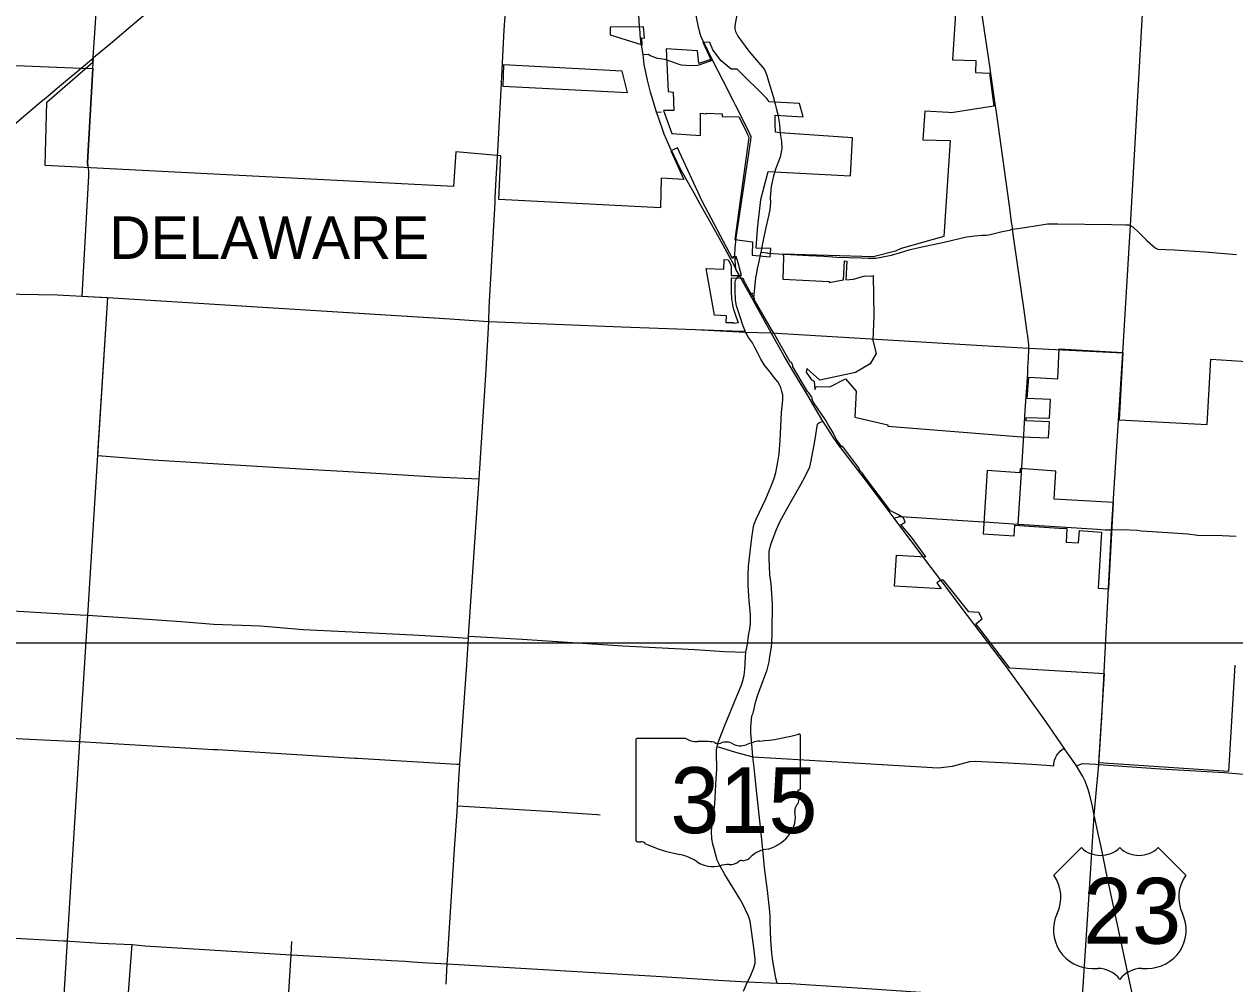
# Model space of a CAD drawing. Extents: x 1729596 to 1925846, y 659247 to 911751.
# Drawn here: x 1796200 to 1821771, y 807237 to 827504 of the extents above; entities that cross this region are included whole.
import ezdxf

# ---------------------------------------------------------------- set-up
doc = ezdxf.new("R2010")
doc.units = 0
for name, color, linetype in [('GM_X_City_Street', 7, 'Continuous'), ('GM_X_Corporation', 7, 'Continuous'), ('GM_X_County_Road', 7, 'Continuous'), ('GM_X_State_Route', 7, 'Continuous'), ('GM_X_State_Shield', 7, 'Continuous'), ('GM_X_Township', 7, 'Continuous'), ('GM_X_Township_Road', 7, 'Continuous'), ('GM_X_Township_Text', 7, 'Continuous'), ('GM_X_US_Route', 7, 'Continuous'), ('GM_X_US_Shield', 7, 'Continuous'), ('SH_Data', 7, 'Continuous')]:
    doc.layers.add(name, color=color, linetype=linetype)

msp = doc.modelspace()

# ---------------------------------------------------------------- linework, layer by layer
at = {"layer": 'GM_X_City_Street'}
for points in [[(1810506, 827220), (1810502, 827229), (1810482, 827281), (1810461, 827356), (1810438, 827474), (1810238, 828490), (1810225, 828549), (1810117, 829066), (1810105, 829126), (1810080, 829357), (1810068, 829471), (1810135, 830154), (1810144, 830257), (1810215, 830861), (1810235, 831013), (1810251, 831109), (1810267, 831292), (1810283, 831379)], [(1806208, 824940), (1806284, 826252), (1806292, 826406), (1806341, 827386), (1806384, 828059), (1806393, 828209), (1806439, 829079), (1806485, 829730)], [(1811339, 828131), (1811336, 828114), (1811291, 827864), (1811232, 827586), (1811211, 827467), (1811213, 827409), (1811226, 827353), (1811276, 827254), (1811353, 827144), (1811508, 826935), (1811666, 826747), (1811796, 826596), (1811839, 826549), (1811877, 826439), (1812017, 825974), (1812059, 825816)], [(1797542, 824510), (1797538, 824584), (1797648, 826566), (1797666, 826798)], [(1809272, 826861), (1809388, 826870), (1809425, 826840), (1809572, 826785), (1809634, 826782), (1809723, 826766), (1809774, 826750)], [(1809554, 825645), (1809661, 825653)], [(1812124, 825562), (1812156, 825394), (1812169, 825198)], [(1812067, 824435), (1812027, 824300), (1811979, 824075), (1811956, 823838), (1811961, 823737), (1811950, 823584), (1811912, 823418), (1811863, 823209), (1811821, 823014), (1811788, 822838)], [(1811218, 822539), (1811212, 822624), (1811214, 822783), (1811229, 822907)], [(1812232, 822643), (1812134, 822648), (1811916, 822664)], [(1811748, 822631), (1811720, 822495), (1811680, 822334), (1811660, 822220), (1811644, 822150), (1811628, 821928), (1811606, 821726)], [(1817270, 818144), (1817313, 818821)], [(1814830, 817099), (1816459, 816996)], [(1818869, 816837), (1819032, 816826), (1819169, 816826), (1819183, 816827)], [(1819183, 816827), (1819368, 816835), (1819716, 816815), (1819794, 816805), (1820031, 816793), (1820776, 816743), (1820982, 816713), (1821507, 816705), (1821800, 816689)]]:
    msp.add_lwpolyline(points, dxfattribs=at)
at = {"layer": 'GM_X_Corporation'}
for points in [[(1821774, 813966), (1821636, 811724), (1818900, 811901), (1819016, 813785), (1817020, 813906), (1816383, 814734), (1816301, 814842), (1816435, 814943), (1816366, 815082), (1816155, 815095), (1815617, 815760), (1815561, 815764), (1815479, 815702), (1815572, 815578), (1814586, 815636), (1814625, 816291), (1815246, 816252), (1814939, 816670), (1814720, 816934), (1814753, 816955), (1814811, 816988), (1814776, 817076), (1814667, 817139), (1814496, 817226), (1813955, 817945), (1813903, 818031), (1813839, 818093), (1813831, 818102), (1813843, 818112), (1813482, 818591), (1813470, 818581), (1813351, 818740), (1813288, 818875), (1813189, 819034), (1813124, 819146), (1812881, 819505), (1812836, 819583), (1812849, 819591), (1812841, 819604), (1812840, 819626), (1812822, 819647), (1812774, 819718), (1812742, 819743), (1812429, 820284), (1812442, 820292), (1812415, 820338), (1812417, 820354), (1812400, 820364), (1812387, 820356), (1812151, 820764), (1812047, 820960), (1811983, 821059), (1811619, 821689), (1811632, 821697), (1811579, 821781), (1811582, 821822), (1811562, 821811), (1811560, 821797), (1811397, 822105), (1811403, 822125), (1811382, 822132), (1811133, 822137), (1811133, 821868), (1811134, 821801), (1811137, 821758), (1811143, 821693), (1811151, 821634), (1811163, 821568), (1811177, 821507), (1811194, 821445), (1811208, 821399), (1811222, 821359), (1811281, 821198), (1811184, 821182), (1811183, 821194), (1811026, 821197), (1811031, 821344), (1810779, 821357), (1810605, 822346), (1810980, 822327), (1810984, 822534), (1811067, 822528), (1811119, 822437), (1811132, 822394), (1811132, 822197), (1811349, 822193), (1811259, 822541), (1811249, 822540), (1811248, 822594), (1811168, 822593), (1811175, 822563), (1811162, 822555), (1810518, 823765), (1809997, 824891), (1809861, 824827), (1810131, 824227), (1809651, 824252), (1809640, 823625), (1806224, 823803), (1806265, 824722), (1805316, 824805), (1805265, 824074), (1796641, 824518), (1796676, 825855), (1797651, 826702), (1797775, 828578)], [(1815869, 827729), (1815809, 826748), (1816301, 826739), (1816293, 826483), (1816593, 826467), (1816684, 825773), (1815779, 825630), (1815726, 825640), (1815222, 825670), (1815180, 825063), (1815759, 825045), (1815628, 823017), (1814722, 822767), (1814602, 822713), (1814135, 822592), (1812230, 822645), (1812230, 822615), (1812238, 822614), (1812238, 822584), (1812222, 822121), (1813205, 822069), (1813204, 822049), (1813466, 822100), (1813508, 822104), (1813529, 822505), (1813579, 822502), (1813558, 822108), (1813717, 822121), (1813958, 822191), (1814077, 822182), (1814129, 822194), (1814144, 821346), (1814126, 820821), (1814199, 820548), (1814067, 820328), (1813758, 820150), (1813004, 819989), (1812733, 820233), (1812719, 820154), (1812829, 819996), (1812884, 819964), (1812897, 819788), (1812927, 819853), (1813214, 819848), (1813547, 820011), (1813776, 819756), (1813747, 819206), (1814444, 819045), (1814443, 819012), (1817265, 818792), (1817839, 818766), (1817858, 819105), (1817359, 819129), (1817368, 819200), (1817858, 819180), (1817881, 819577), (1817386, 819598), (1817424, 820049), (1818033, 820014), (1818062, 820649), (1819407, 820569), (1819331, 819147), (1821186, 819052), (1821268, 820431), (1822355, 820361)]]:
    msp.add_lwpolyline(points, dxfattribs=at)
for points in [[(1808579, 827440), (1808580, 827277), (1809256, 827069), (1809243, 827216), (1809303, 827211), (1809278, 827445)], [(1810680, 827120), (1810555, 827125), (1810531, 827123), (1810705, 826759), (1810448, 826674), (1810424, 826940), (1809760, 826986), (1809802, 826080), (1809910, 826070), (1809921, 825683), (1809702, 825683), (1809880, 825193), (1810482, 825151), (1810482, 825622), (1810610, 825608), (1810614, 825626), (1810943, 825609), (1810942, 825555), (1811292, 825549), (1811441, 825259), (1811467, 825200), (1811504, 825116), (1811497, 825064), (1811212, 822957), (1811584, 822905), (1811579, 822626), (1811958, 822592), (1811972, 822769), (1811662, 822777), (1811687, 823176), (1811759, 823803), (1811913, 824395), (1813652, 824301), (1813695, 825106), (1812168, 825213), (1812072, 825227), (1812064, 825391), (1812060, 825586), (1812655, 825545), (1812574, 825827), (1811933, 825865), (1811884, 825933), (1811257, 826553), (1811133, 826557), (1810925, 826731), (1810749, 826965)], [(1806310, 826192), (1808940, 826058), (1808827, 826510), (1806327, 826644)], [(1816458, 816743), (1817110, 816700), (1817124, 816923), (1817642, 816889), (1818164, 816853), (1818164, 816858), (1818165, 816858), (1818225, 816854), (1818211, 816566), (1818471, 816549), (1818489, 816810), (1818956, 816777), (1818886, 815593), (1819113, 815579), (1819207, 817399), (1817955, 817469), (1817994, 818067), (1817238, 818118), (1817233, 818032), (1816544, 818075)]]:
    msp.add_lwpolyline(points, close=True, dxfattribs=at)
at = {"layer": 'GM_X_County_Road'}
for points in [[(1815650, 832818), (1815681, 832754), (1815696, 832701), (1815707, 832636), (1815724, 832514), (1815839, 831685), (1815910, 831182), (1815924, 831087), (1815997, 830585), (1816596, 826570), (1816611, 826462)], [(1810530, 827173), (1810506, 827220)], [(1811229, 822907), (1811238, 822991), (1811547, 825057), (1811556, 825124), (1811513, 825220), (1811486, 825280), (1811221, 825797), (1811181, 825876), (1810967, 826310), (1810735, 826755), (1810555, 827125), (1810530, 827173)], [(1816611, 826462), (1816709, 825776), (1816721, 825692)], [(1816721, 825692), (1817014, 823620), (1817048, 823324), (1817073, 823174), (1817376, 823219), (1817730, 823275), (1817816, 823287), (1818034, 823286), (1819167, 823275), (1819464, 823265), (1819525, 823263), (1819568, 823254)], [(1806145, 823736), (1806150, 823836), (1806167, 824235), (1806208, 824940)], [(1806012, 821223), (1806020, 821521), (1806145, 823736)], [(1819568, 823254), (1819571, 823253), (1819619, 823227), (1819753, 823095), (1819916, 822937), (1820089, 822781), (1820144, 822756), (1820314, 822745), (1820495, 822735), (1821138, 822696), (1821809, 822641)], [(1811226, 822434), (1811220, 822504), (1811218, 822539)], [(1811235, 822329), (1811226, 822434)], [(1805110, 807232), (1805136, 807661), (1805154, 807942), (1805164, 808090), (1805292, 810078), (1805346, 810873), (1805352, 810999), (1805373, 811438), (1805385, 811671), (1805404, 811873), (1805495, 813180), (1805546, 813974), (1805583, 814537), (1805585, 814578), (1805737, 816876), (1805812, 817899), (1805957, 820207), (1806012, 821223)], [(1814573, 817073), (1814690, 817108), (1814830, 817099)], [(1816459, 816996), (1816476, 816995), (1817194, 816947), (1818869, 816837)], [(1818431, 811839), (1818555, 811891), (1818693, 811885), (1818834, 811875)], [(1818834, 811875), (1818898, 811871), (1820200, 811779), (1821551, 811700), (1822928, 811578), (1824804, 811444), (1826371, 811335), (1826943, 811293), (1828599, 811230), (1828871, 811205), (1830463, 811131), (1832006, 811013), (1832221, 811077), (1832807, 811061), (1833745, 811003), (1833929, 810990)], [(1791747, 808435), (1793395, 808348), (1794980, 808260), (1797031, 808146), (1797107, 808141), (1797153, 808138)], [(1797153, 808138), (1797813, 808094), (1798478, 808064), (1798746, 808039), (1801838, 807850), (1803855, 807737), (1803954, 807731), (1804251, 807713), (1804397, 807702), (1804736, 807682), (1805136, 807661), (1806811, 807563), (1808119, 807486), (1809547, 807399), (1810973, 807310), (1811477, 807276), (1812106, 807251), (1812390, 807244), (1812704, 807223), (1813792, 807154), (1815652, 807028), (1817412, 806933), (1818544, 806864), (1818913, 806840)], [(1801838, 807850), (1801854, 808132)], [(1798065, 800600), (1798320, 804569), (1798319, 804604), (1798313, 804638), (1798300, 804669), (1798280, 804702), (1798255, 804766), (1798245, 804805), (1798244, 804890), (1798409, 807145), (1798478, 808064)], [(1802014, 803669), (1802020, 803715), (1802050, 803896), (1802085, 804077), (1802143, 804374), (1802164, 804595), (1802153, 804796), (1802119, 804993), (1802057, 805167), (1801945, 805481), (1801815, 805789), (1801757, 806010), (1801735, 806174), (1801838, 807850)]]:
    msp.add_lwpolyline(points, dxfattribs=at)
at = {"layer": 'GM_X_State_Route'}
for points in [[(1811226, 822091), (1811226, 822093), (1811237, 822121), (1811244, 822133)], [(1811244, 822133), (1811248, 822139), (1811271, 822169), (1811307, 822197)], [(1811447, 820981), (1811439, 820998), (1811426, 821030), (1811387, 821129), (1811315, 821347), (1811248, 821559), (1811221, 821676), (1811215, 821879), (1811220, 822066), (1811226, 822091)], [(1811396, 807084), (1811477, 807276), (1811532, 807384), (1811613, 807576), (1811639, 807676), (1811643, 807748), (1811620, 807949), (1811532, 808561), (1811500, 808662), (1811375, 808930), (1811317, 809033), (1810997, 809547), (1810899, 809721), (1810839, 809851), (1810772, 810087), (1810748, 810186), (1810723, 810300), (1810719, 810451), (1810730, 810638), (1810750, 810726), (1810788, 811039), (1810819, 811571), (1810831, 811764), (1810832, 811874), (1810825, 812009), (1810821, 812072), (1810825, 812175), (1810836, 812251), (1810851, 812314), (1810876, 812387), (1810989, 812675), (1811252, 813309), (1811341, 813530), (1811373, 813618), (1811406, 813748), (1811418, 813816), (1811425, 813877), (1811430, 814007), (1811436, 814142), (1811445, 814240), (1811468, 814373), (1811509, 814626), (1811524, 814730), (1811538, 814850), (1811540, 815020), (1811534, 815116), (1811513, 815320), (1811494, 815653), (1811493, 815874), (1811500, 816058), (1811569, 816658), (1811588, 816798), (1811608, 816893), (1811627, 816965), (1811662, 817048), (1811862, 817482), (1812003, 817815), (1812048, 817938), (1812078, 818035), (1812115, 818218), (1812145, 818431), (1812171, 818711), (1812195, 819301), (1812222, 819571), (1812222, 819672), (1812205, 819749), (1812182, 819828), (1812152, 819889), (1812117, 819951), (1812041, 820044), (1811961, 820146), (1811840, 820303), (1811759, 820430), (1811689, 820570), (1811636, 820673), (1811584, 820775), (1811498, 820885), (1811447, 820981)]]:
    msp.add_lwpolyline(points, dxfattribs=at)
at = {"layer": 'GM_X_State_Shield'}
for p, q in [((1810173, 812420), (1809154, 812420)), ((1810173, 812420), (1809154, 812420)), ((1812600, 811367), (1812600, 812472)), ((1812600, 811367), (1812600, 812472)), ((1809119, 812383), (1809119, 810270)), ((1809119, 812383), (1809119, 810270)), ((1812599, 811367), (1812600, 811367)), ((1812599, 811367), (1812600, 811367))]:
    msp.add_line(p, q, dxfattribs=at)
for centre, major_axis, start_param, end_param in [((1809159, 812388), (40.3, 0), 1.712693, 3.28349), ((1809159, 812388), (40.3, 0), 1.712693, 3.28349), ((1810416, 812665), (391, 0), 4.042523, 4.731795), ((1810416, 812665), (391, 0), 4.042523, 4.731795), ((1811360, 815301), (3691, 0), 4.814394, 5.042369), ((1811360, 815301), (3691, 0), 4.814394, 5.042369), ((1812561, 812477), (38.7, 0), 6.141152, 7.989035), ((1812561, 812477), (38.7, 0), 6.141152, 7.989035), ((1810545, 811233), (1404, 0), 1.404758, 1.657858), ((1810545, 811233), (1404, 0), 1.404758, 1.657858), ((1810864, 812399), (113, 0), 3.836095, 5.185415), ((1810864, 812399), (113, 0), 3.836095, 5.185415), ((1811030, 812155), (235, 0), 0.950623, 2.079405), ((1811030, 812155), (235, 0), 0.950623, 2.079405), ((1811332, 812490), (282, 0), 4.081561, 5.145723), ((1811332, 812490), (282, 0), 4.081561, 5.145723), ((1811831, 811774), (743, 0), 1.699011, 2.107814), ((1811831, 811774), (743, 0), 1.699011, 2.107814), ((1812591, 811286), (60, 0), 1.883978, 3.671073), ((1812591, 811286), (60, 0), 1.883978, 3.671073), ((1812209, 811146), (360, 0), 5.934695, 6.695948), ((1812209, 811146), (360, 0), 5.934695, 6.695948), ((1812558, 811362), (41.5, 0), 5.05454, 6.418171), ((1812558, 811362), (41.5, 0), 5.05454, 6.418171), ((1812739, 810904), (262, 0), 2.387724, 3.262537), ((1812739, 810904), (262, 0), 2.387724, 3.262537), ((1811567, 810763), (923, 0), 5.101752, 6.440018), ((1811567, 810763), (923, 0), 5.101752, 6.440018), ((1809160, 810266), (40.7, 0), 3.00124, 4.508301), ((1809160, 810266), (40.7, 0), 3.00124, 4.508301), ((1809166, 810482), (310, 0), 4.665946, 4.897461), ((1809166, 810482), (310, 0), 4.665946, 4.897461), ((1809229, 810148), (112, 0), 0.519207, 1.627899), ((1809229, 810148), (112, 0), 0.519207, 1.627899), ((1810642, 812047), (2665, 0), 4.195997, 4.488961), ((1810642, 812047), (2665, 0), 4.195997, 4.488961), ((1809848, 809321), (834, 0), 0.823519, 1.323587), ((1809848, 809321), (834, 0), 0.823519, 1.323587), ((1811315, 810065), (298, 0), 4.937069, 5.64225), ((1811315, 810065), (298, 0), 4.937069, 5.64225), ((1811956, 809677), (506, 0), 1.647645, 2.488434), ((1811956, 809677), (506, 0), 1.647645, 2.488434), ((1810750, 810138), (529, 0), 4.026481, 4.996735), ((1810750, 810138), (529, 0), 4.026481, 4.996735), ((1811056, 809407), (435, 0), 1.495662, 1.94098), ((1811056, 809407), (435, 0), 1.495662, 1.94098), ((1811094, 809980), (282, 0), 4.691044, 5.507374), ((1811094, 809980), (282, 0), 4.691044, 5.507374), ((1811349, 809775), (79.4, 0), 1.147584, 2.315152), ((1811349, 809775), (79.4, 0), 1.147584, 2.315152)]:
    msp.add_ellipse(centre, major_axis=major_axis, ratio=0.8, start_param=start_param, end_param=end_param, dxfattribs=at)
at = {"layer": 'GM_X_Township'}
for points in [[(1818544, 806864), (1818726, 809558), (1818800, 810798), (1818859, 811418), (1818898, 811871), (1818966, 812859), (1819169, 816826), (1819403, 820562), (1819571, 823253), (1819973, 830336), (1820000, 830812), (1820182, 834021), (1820873, 833984), (1824840, 833781)], [(1788529, 827772), (1792915, 827502), (1795894, 827235), (1795858, 826641), (1797406, 826576), (1797648, 826566), (1797538, 824584), (1797542, 824510), (1797556, 824405), (1797555, 824304), (1797417, 821763), (1797959, 821729), (1797746, 818394), (1797534, 815021), (1797366, 812352), (1797107, 808141), (1796898, 804715)], [(1797959, 821729), (1805087, 821285), (1806012, 821223), (1808814, 821113), (1810371, 821058), (1811439, 820998), (1811977, 820984), (1816437, 820719), (1817422, 820661), (1819403, 820562)]]:
    msp.add_lwpolyline(points, dxfattribs=at)
at = {"layer": 'GM_X_Township_Road'}
for points in [[(1809774, 826750), (1809808, 826739), (1809950, 826691), (1810029, 826662), (1810079, 826649), (1810185, 826637), (1810382, 826632), (1810424, 826636), (1810455, 826644), (1810697, 826732), (1810735, 826755)], [(1812059, 825816), (1812082, 825733), (1812117, 825600), (1812124, 825562)], [(1812169, 825198), (1812173, 825150), (1812194, 825026), (1812201, 824882), (1812171, 824694), (1812069, 824441), (1812067, 824435)], [(1797542, 824510), (1797556, 824405), (1797555, 824304), (1797417, 821763)], [(1817073, 823174), (1817003, 823145), (1816831, 823109), (1816579, 823050), (1816518, 823043), (1816429, 823038), (1816279, 823027), (1816104, 823009), (1815633, 822894), (1815134, 822786), (1814883, 822730), (1814700, 822678), (1814511, 822622), (1814269, 822570), (1814184, 822554), (1814027, 822554), (1813877, 822560), (1813626, 822567), (1813365, 822580), (1813087, 822600), (1812773, 822614), (1812270, 822641), (1812232, 822643)], [(1817422, 820643), (1817422, 820661), (1817420, 820732), (1817398, 820917), (1817377, 821042), (1817319, 821461), (1817102, 822974), (1817073, 823174)], [(1811788, 822838), (1811759, 822683), (1811748, 822631)], [(1811916, 822664), (1811901, 822665), (1811759, 822683)], [(1792562, 822063), (1793900, 821979), (1795708, 821807), (1796906, 821790), (1797417, 821763)], [(1797417, 821763), (1797934, 821731)], [(1797959, 821729), (1797748, 818428)], [(1797934, 821731), (1797959, 821729), (1805080, 821285)], [(1811606, 821726), (1811600, 821672)], [(1805080, 821285), (1805087, 821285), (1806012, 821223)], [(1806012, 821223), (1806012, 821223), (1808814, 821113), (1810371, 821058), (1811348, 821023), (1811426, 821030)], [(1817313, 818821), (1817322, 818966), (1817346, 819339), (1817376, 819835), (1817397, 820137), (1817400, 820253), (1817417, 820451), (1817422, 820643)], [(1812106, 807251), (1812076, 807356), (1812013, 807718), (1811995, 807882), (1811968, 808155), (1811955, 808538), (1811959, 808669), (1811946, 808826), (1811900, 809208), (1811835, 809684), (1811797, 810144), (1811750, 810551), (1811677, 811253), (1811649, 811527), (1811621, 811808), (1811589, 812029), (1811561, 812387), (1811545, 812525), (1811545, 812663), (1811569, 812896), (1811599, 812955), (1811649, 813180), (1811695, 813343), (1811808, 813640), (1811891, 813865), (1811933, 814036), (1811953, 814153), (1811974, 814267), (1811986, 814348), (1811990, 814445), (1811996, 814631), (1812001, 814693), (1812003, 815248), (1812001, 815365), (1811975, 815685), (1811950, 815872), (1811933, 816216), (1811939, 816364), (1811969, 816517), (1812081, 816818), (1812169, 817011), (1812315, 817277), (1812437, 817486), (1812517, 817636), (1812610, 817797), (1812701, 817964), (1812797, 818152), (1812824, 818279), (1812897, 818699), (1812958, 819056), (1812980, 819079), (1812998, 819090), (1813066, 819123)], [(1797748, 818428), (1797746, 818394), (1798913, 818302), (1802044, 818116), (1802541, 818082), (1802940, 818062), (1804889, 817941), (1805812, 817899)], [(1817194, 816947), (1817270, 818144)], [(1792152, 815352), (1792194, 815348), (1792538, 815327), (1793017, 815298), (1794320, 815218), (1795831, 815124), (1797378, 815030)], [(1797378, 815030), (1797534, 815021), (1798606, 814949), (1799518, 814890), (1800197, 814834), (1801192, 814794), (1802091, 814720), (1803125, 814672), (1804412, 814610), (1805036, 814572), (1805583, 814537)], [(1805585, 814578), (1806228, 814543), (1806718, 814514), (1808844, 814372), (1810367, 814300), (1810990, 814255), (1811445, 814240)], [(1791996, 812680), (1792135, 812671), (1792361, 812658), (1792900, 812626), (1793503, 812590), (1794528, 812511), (1796172, 812413), (1797338, 812354)], [(1797338, 812354), (1797366, 812352), (1800195, 812188), (1800284, 812182), (1803182, 812004), (1803241, 812000), (1804512, 811927), (1805331, 811878), (1805404, 811873)], [(1810836, 812251), (1811225, 812129), (1811589, 812029), (1812196, 811994), (1813137, 811939), (1815506, 811796), (1815806, 811835), (1816176, 811929), (1816288, 811941), (1816986, 811903), (1817486, 811876), (1817791, 811853), (1817949, 811843), (1817951, 811892), (1817965, 811963), (1817985, 812011), (1818003, 812050), (1818032, 812092), (1818052, 812117), (1818085, 812151), (1818127, 812183), (1818168, 812215)], [(1805352, 810999), (1807012, 810894), (1807261, 810881), (1807355, 810875), (1808303, 810814), (1808367, 810809)]]:
    msp.add_lwpolyline(points, dxfattribs=at)
at = {"layer": 'GM_X_US_Route'}
for points in [[(1797621, 826760), (1797666, 826798), (1798064, 827135), (1798491, 827497), (1799248, 828136), (1799732, 828551), (1800024, 828792), (1800425, 829142)], [(1809214, 827282), (1809209, 827339), (1809200, 827447), (1809185, 827707)], [(1809236, 827071), (1809235, 827075), (1809220, 827214), (1809214, 827282)], [(1809539, 825695), (1809427, 826070), (1809364, 826320), (1809297, 826652), (1809272, 826861), (1809236, 827071)], [(1796695, 825983), (1796802, 826075), (1796947, 826193), (1797406, 826576), (1797621, 826760)], [(1792508, 822464), (1792590, 822534), (1793050, 822917), (1793314, 823141), (1793805, 823550), (1794289, 823956), (1794815, 824398), (1795038, 824581), (1795987, 825387), (1796517, 825835), (1796631, 825927), (1796695, 825983)], [(1809871, 824842), (1809868, 824846), (1809721, 825180), (1809589, 825557), (1809554, 825645), (1809539, 825695)], [(1810349, 823936), (1810231, 824145), (1810052, 824472), (1809871, 824842)], [(1810745, 823229), (1810480, 823705), (1810349, 823936)], [(1811356, 822110), (1811307, 822197), (1811235, 822329), (1811210, 822389), (1810886, 822980), (1810752, 823218), (1810745, 823229)], [(1811380, 822066), (1811356, 822110)], [(1812274, 820456), (1812250, 820496), (1811977, 820984), (1811799, 821302), (1811600, 821672), (1811380, 822066)], [(1814573, 817073), (1813939, 817914), (1813382, 818649), (1813272, 818802), (1813124, 819034), (1813066, 819123), (1812906, 819393), (1812721, 819714), (1812534, 820020), (1812274, 820456)], [(1815183, 816265), (1814573, 817073)], [(1815247, 816180), (1815183, 816265)], [(1815568, 815755), (1815561, 815764), (1815247, 816180)], [(1818772, 810948), (1818759, 811018), (1818704, 811246), (1818662, 811380), (1818602, 811532), (1818561, 811618), (1818501, 811720), (1818431, 811839), (1818397, 811882), (1818191, 812181), (1818168, 812215), (1817777, 812779), (1817339, 813398), (1816925, 813961), (1816128, 815013), (1815568, 815755)], [(1819598, 807070), (1819046, 809639), (1818948, 810127), (1818889, 810378), (1818800, 810798), (1818772, 810948)]]:
    msp.add_lwpolyline(points, dxfattribs=at)
at = {"layer": 'GM_X_US_Shield'}
for p, q in [((1818530, 810114), (1817950, 809534)), ((1818530, 810114), (1817950, 809534)), ((1820735, 809534), (1820154, 810114)), ((1820735, 809534), (1820154, 810114)), ((1818762, 807561), (1818878, 807561)), ((1818762, 807561), (1818878, 807561)), ((1819806, 807561), (1819922, 807561)), ((1819806, 807561), (1819922, 807561))]:
    msp.add_line(p, q, dxfattribs=at)
for centre, radius, start, end in [((1818936, 810528), 580, 225.573, 314.427), ((1818936, 810528), 580, 225.573, 314.427), ((1819748, 810528), 580, 225.573, 314.427), ((1819748, 810528), 580, 225.573, 314.427), ((1817285, 809068), 812, 334.5471, 35.0009), ((1817285, 809068), 812, 334.5471, 35.0009), ((1821400, 809068), 812, 144.9991, 205.4529), ((1821400, 809068), 812, 144.9991, 205.4529), ((1818753, 808373), 812, 154.8319, 270.6383), ((1818753, 808373), 812, 154.8319, 270.6383), ((1819931, 808373), 812, 269.3617, 25.1681), ((1819931, 808373), 812, 269.3617, 25.1681), ((1818878, 806981), 580, 36.8699, 90), ((1818878, 806981), 580, 36.8699, 90), ((1819806, 806981), 580, 90, 143.1301), ((1819806, 806981), 580, 90, 143.1301)]:
    msp.add_arc(centre, radius, start, end, dxfattribs=at)
at = {"layer": 'SH_Data'}
msp.add_line((1828599, 814428), (1752099, 814428), dxfattribs=at)

# ---------------------------------------------------------------- texts
at = {"layer": 'GM_X_State_Shield'}
msp.add_text('315', height=1392.2, dxfattribs=at).set_placement((1809849, 810419))
msp.add_text('315', height=1392.2, dxfattribs=at).set_placement((1809849, 810419))
at = {"layer": 'GM_X_Township_Text'}
msp.add_text('DELAWARE', height=900, rotation=0, dxfattribs=at).set_placement((1798000, 822547))
at = {"layer": 'GM_X_US_Shield'}
msp.add_text('23', height=1392.2, dxfattribs=at).set_placement((1818567, 808083))
msp.add_text('23', height=1392.2, dxfattribs=at).set_placement((1818567, 808083))

doc.saveas('drawing.dxf')
